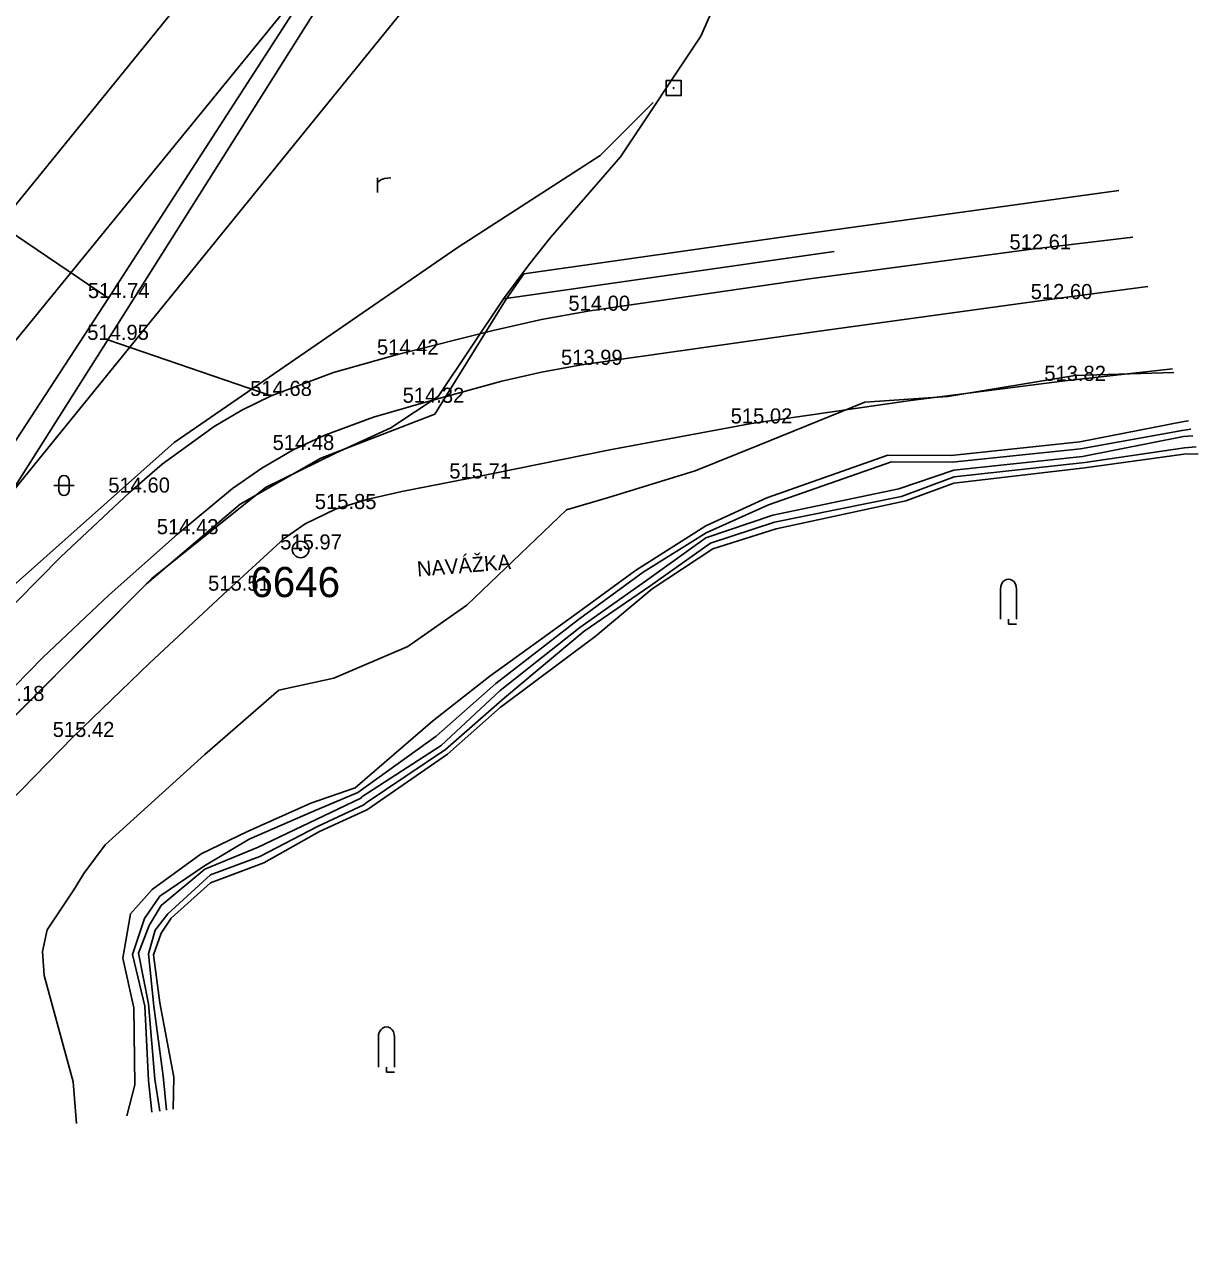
# Model space of a CAD drawing. Extents: x -669393 to -668650, y -1126925 to -1126294.
# Drawn here: x -668708.7 to -668650.3, y -1126871.3 to -1126809.8 of the extents above; entities that cross this region are included whole.
import ezdxf

# ---------------------------------------------------------------- set-up
doc = ezdxf.new("R2010")
doc.units = 0
for name, color, linetype in [('G_Bod_tecka', 7, 'Continuous'), ('G_Bod_vyska', 7, 'Continuous'), ('G_Bodove_pole', 7, 'Continuous'), ('G_Breh_Teren', 7, 'Continuous'), ('G_Cesty_Schody', 7, 'Continuous'), ('G_Poznamky_odkaz', 7, 'Continuous'), ('G_Site-Sachty_N', 7, 'Continuous'), ('G_Z_ELsilove_nadz_geodeticky', 7, 'Continuous'), ('G_Z_ELsilove_podz_kotovane', 7, 'Continuous'), ('G_Z_ELsilove_zrusene', 7, 'Continuous'), ('G_Z_SPOJE_nadz_kotovane', 7, 'Continuous'), ('G_Z_SPOJE_podz_kotovane', 7, 'Continuous'), ('G_Zelen-okraj', 7, 'Continuous'), ('G_Zelen-rozhrani', 7, 'Continuous'), ('G_Zelen-Znacky', 7, 'Continuous')]:
    doc.layers.add(name, color=color, linetype=linetype)

msp = doc.modelspace()

# ---------------------------------------------------------------- linework, layer by layer
at = {"layer": 'G_Bod_tecka'}
for p, q in [((-668658.7, -1126820.95), (-668658.7, -1126820.95)), ((-668704.5, -1126823.37), (-668704.5, -1126823.37)), ((-668657.56, -1126823.42), (-668657.56, -1126823.42)), ((-668680.55, -1126824), (-668680.55, -1126824)), ((-668704.53, -1126825.45), (-668704.53, -1126825.45)), ((-668690.12, -1126826.18), (-668690.12, -1126826.18)), ((-668680.96, -1126826.69), (-668680.96, -1126826.69)), ((-668656.92, -1126827.49), (-668656.92, -1126827.49)), ((-668696.41, -1126828.24), (-668696.41, -1126828.24)), ((-668688.84, -1126828.58), (-668688.84, -1126828.58)), ((-668672.5, -1126829.61), (-668672.5, -1126829.61)), ((-668695.31, -1126830.93), (-668695.31, -1126830.93)), ((-668686.58, -1126832.35), (-668686.58, -1126832.35)), ((-668703.45, -1126833.05), (-668703.45, -1126833.05)), ((-668693.21, -1126833.87), (-668693.21, -1126833.87)), ((-668701.07, -1126835.12), (-668701.07, -1126835.12)), ((-668694.94, -1126835.88), (-668694.94, -1126835.88)), ((-668698.58, -1126837.93), (-668698.58, -1126837.93)), ((-668706.25, -1126845.21), (-668706.25, -1126845.21))]:
    msp.add_line(p, q, dxfattribs=at)
at = {"layer": 'G_Bodove_pole'}
for radius in [0.412, 0.05]:
    msp.add_circle((-668694.94, -1126835.88), radius, dxfattribs=at)
at = {"layer": 'G_Breh_Teren'}
for p, q in [((-668704.5, -1126823.37), (-668690.07, -1126801.04)), ((-668689.99, -1126802.38), (-668704.53, -1126825.45)), ((-668714.84, -1126839.23), (-668704.5, -1126823.37)), ((-668704.53, -1126825.45), (-668713.69, -1126839.9))]:
    msp.add_line(p, q, dxfattribs=at)
msp.add_lwpolyline([(-668651.559, -1126826.884), (-668656.92, -1126827.49), (-668664.72, -1126828.48), (-668672.5, -1126829.61), (-668679.55, -1126830.92), (-668686.58, -1126832.35), (-668689.91, -1126833), (-668691.57, -1126833.38), (-668693.21, -1126833.87), (-668694.72, -1126834.6), (-668695.75, -1126835.33), (-668698.58, -1126837.93), (-668702.45, -1126841.53), (-668706.25, -1126845.21), (-668713.94, -1126853.07), (-668717.69, -1126857.1), (-668721.35, -1126861.22), (-668723.18, -1126863.5), (-668725.7, -1126867.09), (-668725.902, -1126867.396)], dxfattribs=at)
at = {"layer": 'G_Cesty_Schody'}
for points in [[(-668735.324, -1126868.801), (-668735.01, -1126868.41), (-668730.21, -1126862.76), (-668725.32, -1126857.18), (-668718.76, -1126849.52), (-668712.2, -1126841.85), (-668710.13, -1126839.55), (-668706.86, -1126836.25), (-668703.45, -1126833.05), (-668701.83, -1126831.64), (-668699.24, -1126829.76), (-668697.86, -1126828.95), (-668696.41, -1126828.24), (-668693.3, -1126827.08), (-668690.12, -1126826.18), (-668685.36, -1126824.98), (-668682.96, -1126824.44), (-668680.55, -1126824), (-668669.63, -1126822.41), (-668658.7, -1126820.95), (-668653.537, -1126820.34)], [(-668731.145, -1126868.178), (-668728.25, -1126864.58), (-668723.26, -1126858.55), (-668716.67, -1126850.9), (-668709.87, -1126843.42), (-668707.76, -1126841.25), (-668704.47, -1126838.14), (-668701.07, -1126835.12), (-668698.32, -1126832.85), (-668696.86, -1126831.83), (-668695.31, -1126830.93), (-668693.74, -1126830.19), (-668691.32, -1126829.3), (-668688.84, -1126828.58), (-668684.92, -1126827.51), (-668682.95, -1126827.05), (-668680.96, -1126826.69), (-668669.26, -1126825.03), (-668657.56, -1126823.42), (-668652.797, -1126822.788)]]:
    msp.add_lwpolyline(points, dxfattribs=at)
at = {"layer": 'G_Site-Sachty_N'}
msp.add_lwpolyline([(-668676.755, -1126813.295), (-668676.005, -1126813.295), (-668676.005, -1126812.545), (-668676.755, -1126812.545)], close=True, dxfattribs=at)
msp.add_circle((-668676.38, -1126812.92), 0.02, dxfattribs=at)
at = {"layer": 'G_Z_ELsilove_nadz_geodeticky'}
for points in [[(-668751.765, -1126871.252), (-668668.972, -1126769.268)], [(-668665.878, -1126779.507), (-668738.732, -1126869.309)]]:
    msp.add_lwpolyline(points, dxfattribs=at)
at = {"layer": 'G_Z_ELsilove_podz_kotovane'}
for points in [[(-668706.083, -1126864.442), (-668706.246, -1126862.371), (-668707.693, -1126857.078), (-668707.783, -1126855.882), (-668707.552, -1126854.809), (-668706.226, -1126852.822), (-668705.716, -1126852), (-668704.654, -1126850.572), (-668699.697, -1126846.09), (-668696.014, -1126842.885), (-668693.28, -1126842.285), (-668689.605, -1126840.711), (-668686.662, -1126838.654), (-668681.705, -1126833.903), (-668679.62, -1126833.301), (-668675.308, -1126831.969), (-668672.137, -1126830.687), (-668666.862, -1126828.557), (-668662.747, -1126828.272), (-668656.43, -1126827.228), (-668651.501, -1126827.077)], [(-668703.59, -1126864.07), (-668703.193, -1126862.526), (-668703.235, -1126858.691), (-668703.787, -1126856.214), (-668703.404, -1126854.014), (-668702.328, -1126852.802), (-668699.891, -1126851.018), (-668697.58, -1126849.913), (-668694.437, -1126848.51), (-668692.227, -1126847.739), (-668688.37, -1126844.427), (-668685.523, -1126842.18), (-668681.298, -1126839.14), (-668678.276, -1126836.924), (-668674.782, -1126834.702), (-668671.738, -1126833.303), (-668665.726, -1126831.188), (-668662.568, -1126831.199), (-668656.176, -1126830.524), (-668651.006, -1126829.519), (-668650.773, -1126829.486)], [(-668702.34, -1126863.884), (-668702.51, -1126862.303), (-668702.688, -1126858.602), (-668703.303, -1126856.034), (-668702.7, -1126854.244), (-668701.94, -1126853.137), (-668699.723, -1126851.622), (-668697.504, -1126850.295), (-668694.333, -1126848.914), (-668692.084, -1126847.975), (-668688.197, -1126845.171), (-668685.221, -1126842.543), (-668681.119, -1126839.369), (-668677.896, -1126837.014), (-668674.763, -1126835.054), (-668671.654, -1126833.657), (-668665.542, -1126831.512), (-668662.528, -1126831.532), (-668656.145, -1126830.864), (-668651.083, -1126829.957), (-668650.648, -1126829.9)], [(-668701.604, -1126863.774), (-668701.771, -1126862.087), (-668702.238, -1126858.609), (-668702.508, -1126856.007), (-668702.172, -1126854.817), (-668701.544, -1126854.017), (-668699.426, -1126852.073), (-668696.975, -1126851.155), (-668694.096, -1126849.658), (-668691.789, -1126848.581), (-668691.677, -1126848.489), (-668687.73, -1126845.839), (-668684.795, -1126843.258), (-668680.838, -1126839.939), (-668677.559, -1126837.708), (-668674.546, -1126835.559), (-668671.358, -1126834.516), (-668665.04, -1126833.236), (-668662.429, -1126832.258), (-668655.932, -1126831.555), (-668650.966, -1126830.82), (-668650.386, -1126830.765)], [(-668701.287, -1126863.727), (-668701.241, -1126862.146), (-668701.949, -1126858.441), (-668702.251, -1126856.044), (-668701.883, -1126854.972), (-668701.372, -1126854.221), (-668699.424, -1126852.469), (-668696.776, -1126851.479), (-668694.005, -1126849.919), (-668691.671, -1126848.855), (-668691.617, -1126848.827), (-668687.625, -1126846.06), (-668685.005, -1126843.747), (-668680.287, -1126840.204), (-668677.441, -1126837.832), (-668674.436, -1126835.841), (-668671.275, -1126834.859), (-668664.832, -1126833.464), (-668662.445, -1126832.586), (-668655.922, -1126831.811), (-668650.994, -1126831.138), (-668650.281, -1126831.115)]]:
    msp.add_lwpolyline(points, dxfattribs=at)
at = {"layer": 'G_Z_ELsilove_zrusene'}
msp.add_lwpolyline([(-668701.944, -1126863.825), (-668702.196, -1126862.233), (-668702.514, -1126858.492), (-668703, -1126855.969), (-668702.468, -1126854.596), (-668701.872, -1126853.602), (-668699.709, -1126851.789), (-668697.042, -1126850.691), (-668694.159, -1126849.311), (-668691.939, -1126848.256), (-668691.885, -1126848.187), (-668687.943, -1126845.634), (-668685.014, -1126842.895), (-668681.052, -1126839.769), (-668677.781, -1126837.454), (-668674.78, -1126835.301), (-668671.453, -1126834.167), (-668665.176, -1126832.857), (-668662.448, -1126831.931), (-668656.046, -1126831.255), (-668651.013, -1126830.26), (-668650.55, -1126830.223)], dxfattribs=at)
msp.add_lwpolyline([(-668701.944, -1126863.825), (-668702.196, -1126862.233), (-668702.514, -1126858.492), (-668703, -1126855.969), (-668702.468, -1126854.596), (-668701.872, -1126853.602), (-668699.709, -1126851.789), (-668697.042, -1126850.691), (-668694.159, -1126849.311), (-668691.939, -1126848.256), (-668691.885, -1126848.187), (-668687.943, -1126845.634), (-668685.014, -1126842.895), (-668681.052, -1126839.769), (-668677.781, -1126837.454), (-668674.78, -1126835.301), (-668671.453, -1126834.167), (-668665.176, -1126832.857), (-668662.448, -1126831.931), (-668656.046, -1126831.255), (-668651.013, -1126830.26), (-668650.55, -1126830.223)], dxfattribs=at)
at = {"layer": 'G_Z_SPOJE_nadz_kotovane'}
msp.add_lwpolyline([(-668667.439, -1126774.342), (-668745.726, -1126870.351)], dxfattribs=at)
at = {"layer": 'G_Z_SPOJE_podz_kotovane'}
for p, q in [((-668683.83, -1126822.16), (-668684.75, -1126823.47)), ((-668688.26, -1126829.15), (-668684.75, -1126823.47)), ((-668693.93, -1126831.34), (-668688.26, -1126829.15)), ((-668697.95, -1126833.63), (-668693.93, -1126831.34)), ((-668702.6, -1126837.59), (-668697.95, -1126833.63)), ((-668716.01, -1126851.01), (-668702.6, -1126837.59))]:
    msp.add_line(p, q, dxfattribs=at)
for points in [[(-668663.045, -1126788.882), (-668670.17, -1126797.52), (-668673, -1126805.72), (-668675.02, -1126810.33), (-668679.02, -1126816.34)], [(-668677.4, -1126813.63), (-668680.03, -1126816.28), (-668687.1, -1126820.84), (-668701.23, -1126830.56), (-668709.37, -1126837.8), (-668728.24, -1126859.59), (-668736.021, -1126868.905)], [(-668679.02, -1126816.34), (-668682.5, -1126820.35), (-668683.58, -1126821.71), (-668684.84, -1126823.41)], [(-668683.83, -1126822.16), (-668670.44, -1126820.26), (-668654.237, -1126818.024)], [(-668684.84, -1126823.41), (-668668.4, -1126821.05)], [(-668729.578, -1126867.944), (-668727.43, -1126865.13), (-668715.5, -1126850.64), (-668708.73, -1126843.75), (-668702.34, -1126837.33), (-668696.68, -1126832.8), (-668693.2, -1126831.09), (-668690.45, -1126829.82), (-668688.09, -1126828.26), (-668684.84, -1126823.41)]]:
    msp.add_lwpolyline(points, dxfattribs=at)
at = {"layer": 'G_Zelen-okraj'}
msp.add_line((-668717.14, -1126814.83), (-668704.5, -1126823.37), dxfattribs=at)
at = {"layer": 'G_Zelen-rozhrani'}
msp.add_line((-668696.41, -1126828.24), (-668704.53, -1126825.45), dxfattribs=at)
at = {"layer": 'G_Zelen-Znacky'}
for p, q in [((-668691.12, -1126818.121), (-668691.12, -1126817.389)), ((-668706.96, -1126832.95), (-668706.96, -1126832.45)), ((-668706.46, -1126832.95), (-668706.46, -1126832.45)), ((-668706.21, -1126832.7), (-668707.21, -1126832.7)), ((-668660.12, -1126839.35), (-668660.12, -1126837.85)), ((-668659.32, -1126837.85), (-668659.32, -1126839.35)), ((-668659.72, -1126839.35), (-668659.72, -1126839.6)), ((-668659.72, -1126839.6), (-668659.32, -1126839.6)), ((-668691.07, -1126861.64), (-668691.07, -1126860.14)), ((-668690.27, -1126860.14), (-668690.27, -1126861.64)), ((-668690.67, -1126861.64), (-668690.67, -1126861.89)), ((-668690.67, -1126861.89), (-668690.27, -1126861.89))]:
    msp.add_line(p, q, dxfattribs=at)
msp.add_lwpolyline([(-668691.12, -1126817.625), (-668691.018, -1126817.53), (-668690.915, -1126817.467), (-668690.758, -1126817.42), (-668690.608, -1126817.397), (-668690.451, -1126817.389)], dxfattribs=at)
for centre, start, end in [((-668706.71, -1126832.45), 0, 180), ((-668706.71, -1126832.95), 180, 0)]:
    msp.add_arc(centre, 0.25, start, end, dxfattribs=at)
for centre in [(-668659.72, -1126837.85), (-668690.67, -1126860.14)]:
    msp.add_ellipse(centre, major_axis=(0, 0.5), ratio=0.8, start_param=4.712389, end_param=7.853982, dxfattribs=at)

# ---------------------------------------------------------------- texts
at = {"layer": 'G_Bod_vyska'}
for s, p in [('512.61', (-668659.674, -1126820.95)), ('514.74', (-668705.522, -1126823.37)), ('512.60', (-668658.618, -1126823.42)), ('514.00', (-668681.616, -1126824)), ('514.95', (-668705.554, -1126825.45)), ('514.42', (-668691.142, -1126826.18)), ('513.99', (-668681.986, -1126826.69)), ('513.82', (-668657.942, -1126827.49)), ('514.68', (-668697.446, -1126828.24)), ('514.32', (-668689.862, -1126828.58)), ('515.02', (-668673.544, -1126829.61)), ('514.48', (-668696.332, -1126830.93)), ('515.71', (-668687.541, -1126832.35)), ('514.60', (-668704.508, -1126833.05)), ('515.85', (-668694.232, -1126833.87)), ('514.43', (-668702.092, -1126835.12)), ('515.97', (-668695.954, -1126835.88)), ('515.51', (-668699.541, -1126837.93)), ('514.18', (-668710.751, -1126843.42)), ('515.42', (-668707.272, -1126845.21))]:
    msp.add_text(s, height=0.75, dxfattribs=at).set_placement(p)
at = {"layer": 'G_Bodove_pole'}
msp.add_text('6646', height=1.5, dxfattribs=at).set_placement((-668697.437, -1126838.25))
at = {"layer": 'G_Poznamky_odkaz'}
msp.add_text('NAVÁŽKA', height=0.75, rotation=4.61316, dxfattribs=at).set_placement((-668689.119, -1126837.233))

doc.saveas('drawing.dxf')
